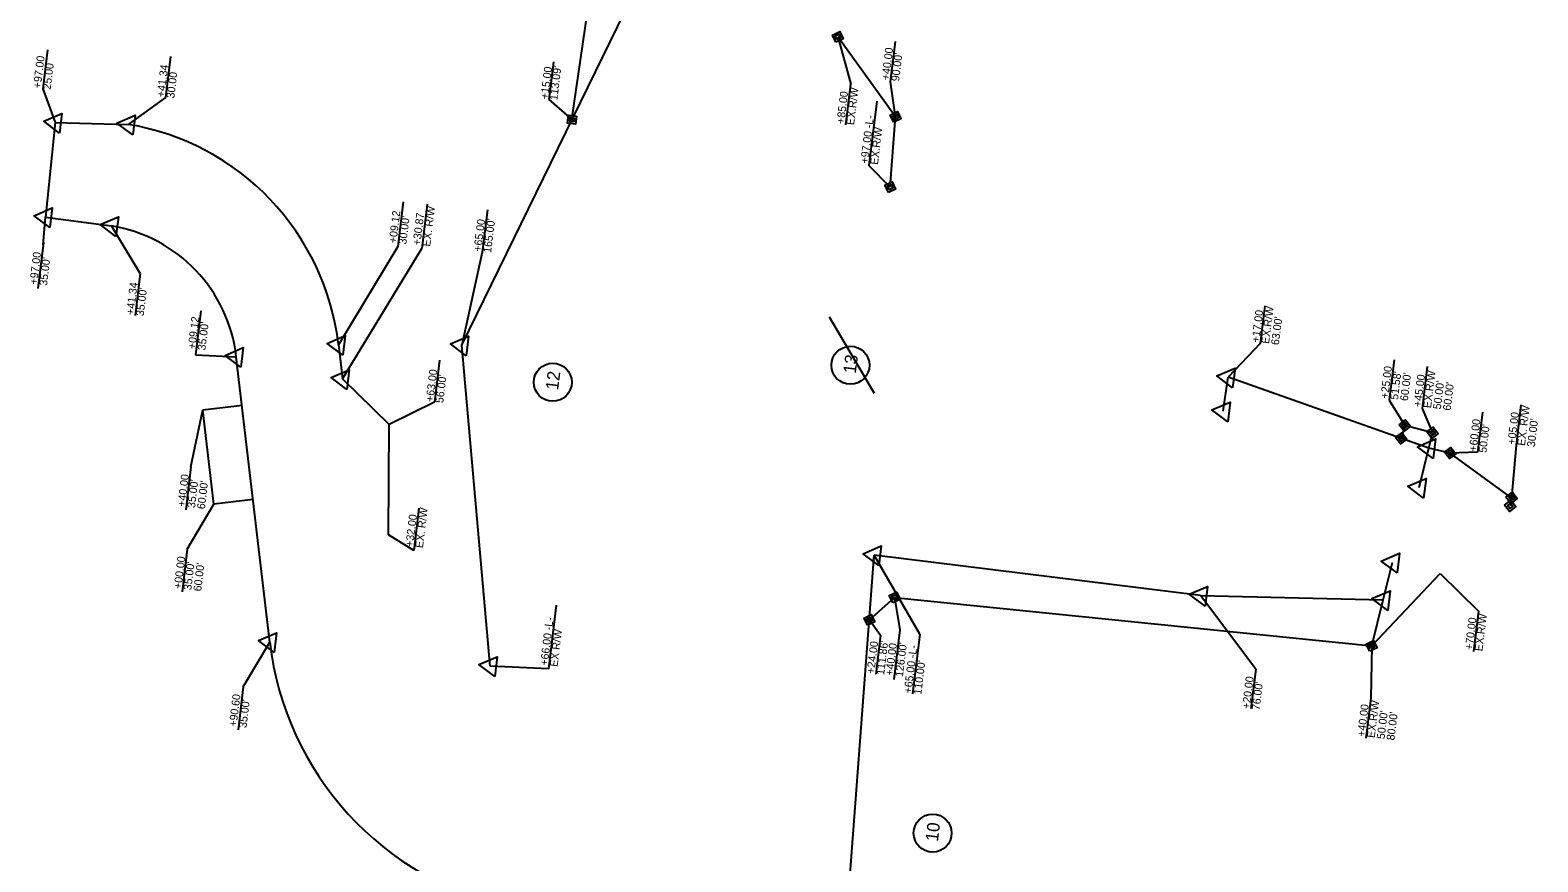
# Model space of a CAD drawing. Extents: x 474184 to 481900, y 489262 to 505659.
# Drawn here: x 480947 to 481900, y 490740 to 491265 of the extents above; entities that cross this region are included whole.
import ezdxf

# ---------------------------------------------------------------- set-up
doc = ezdxf.new("R2010")
doc.units = 0
for name, color, linetype in [('Prop Drainage Structure Box Number Symbol CELL', 7, 'Continuous'), ('Prop Drainage Structure Drop Inlet Grate 2 Wide Slots and Sag Grates 840 22 CELL', 7, 'Continuous'), ('Prop Drainage Structure Outlet Berm Ditch 850 10 Label', 7, 'Continuous'), ('Prop Drainage Structure Pipe CSP 15in', 7, 'Continuous'), ('Prop Drainage Structure Pipe RCP 18in Class IV', 7, 'Continuous'), ('Prop Drainage Structure Pipe RCP 18in Class IV Label', 7, 'Continuous'), ('Prop Drainage Structure Pipe Side Drain 15in Label', 7, 'Continuous'), ('Prop Drainage Structure Pipe Stub Out CELL', 7, 'Continuous'), ('Prop Drainage Structure Plot Symbol 50 Scale', 7, 'Continuous'), ('Prop Earthen Structure Base Ditch Lateral Detail Label', 7, 'Continuous'), ('Prop Earthen Structure False Sump CELL', 7, 'Continuous'), ('Prop Earthen Structure False Sump Label', 7, 'Continuous')]:
    doc.layers.add(name, color=color, linetype=linetype)

msp = doc.modelspace()

# ---------------------------------------------------------------- linework, layer by layer
at = {"layer": 'Prop Drainage Structure Box Number Symbol CELL'}
msp.add_line((481481.1, 491035.35), (481452.82, 491083.62), dxfattribs=at)
at = {"layer": 'Prop Drainage Structure Drop Inlet Grate 2 Wide Slots and Sag Grates 840 22 CELL'}
for p, q in [((481289.91, 491208.53), (481322.37, 491432.91)), ((481845.12, 490997.83), (481831.54, 491000.96)), ((481883.94, 490969.56), (481845.12, 490997.83)), ((481883.94, 490969.56), (481883, 490964.49))]:
    msp.add_line(p, q, dxfattribs=at)
at = {"layer": 'Prop Drainage Structure Outlet Berm Ditch 850 10 Label'}
for p, q in [((481494.51, 491210.18), (481457.98, 491260.76)), ((481491.08, 491165.82), (481494.51, 491210.18)), ((481816.35, 491015.22), (481814.11, 491007.1)), ((481833.89, 491010.67), (481816.35, 491015.22)), ((481831.54, 491000.96), (481833.89, 491010.67)), ((481477.93, 490892.4), (481493.9, 490906.57)), ((481493.9, 490906.57), (481795.45, 490875.96)), ((481795.45, 490875.96), (481802.74, 490905.06))]:
    msp.add_line(p, q, dxfattribs=at)
at = {"layer": 'Prop Drainage Structure Pipe CSP 15in'}
for p, q in [((481465.93, 491053.29), (481465.93, 491053.29)), ((481277.77, 491042.54), (481277.77, 491042.54)), ((481517.9, 490757.64), (481517.9, 490757.64))]:
    msp.add_line(p, q, dxfattribs=at)
for centre in [(481465.93, 491053.29), (481277.77, 491042.54), (481517.9, 490757.64)]:
    msp.add_circle(centre, 12, dxfattribs=at)
at = {"layer": 'Prop Drainage Structure Pipe RCP 18in Class IV'}
for p, q in [((481457.98, 491260.76), (481457.98, 491260.76)), ((481289.91, 491208.53), (481289.91, 491208.53)), ((481494.51, 491210.18), (481494.51, 491210.18)), ((480963.14, 491206.59), (480963.14, 491206.59)), ((481009.43, 491205.47), (481009.43, 491205.47)), ((481491.08, 491165.82), (481491.08, 491165.82)), ((480957.06, 491146.9), (480957.06, 491146.9)), ((480998.85, 491141.33), (480998.85, 491141.33)), ((481142.3, 491066.22), (481142.3, 491066.22)), ((481220.2, 491065.93), (481220.2, 491065.93)), ((481077.74, 491058.66), (481077.74, 491058.66)), ((481704.75, 491045.65), (481704.75, 491045.65)), ((481144.84, 491044.62), (481144.84, 491044.62)), ((481701.64, 491024.2), (481701.64, 491024.2)), ((481816.35, 491015.22), (481816.35, 491015.22)), ((481833.89, 491010.67), (481833.89, 491010.67)), ((481814.11, 491007.1), (481814.11, 491007.1)), ((481831.54, 491000.96), (481831.54, 491000.96)), ((481845.12, 490997.83), (481845.12, 490997.83)), ((481825.49, 490976.02), (481825.49, 490976.02)), ((481883.94, 490969.56), (481883.94, 490969.56)), ((481883, 490964.49), (481883, 490964.49)), ((481481.05, 490933.33), (481481.05, 490933.33)), ((481808.67, 490928.71), (481808.67, 490928.71)), ((481493.9, 490906.57), (481493.9, 490906.57)), ((481687.27, 490907.72), (481687.27, 490907.72)), ((481802.74, 490905.06), (481802.74, 490905.06)), ((481477.93, 490892.4), (481477.93, 490892.4)), ((481098.87, 490878.41), (481098.87, 490878.41)), ((481795.45, 490875.96), (481795.45, 490875.96)), ((481238.27, 490863.24), (481238.27, 490863.24))]:
    msp.add_line(p, q, dxfattribs=at)
for points in [[(480965.95, 491199.95), (480955.99, 491207.47), (480967.47, 491212.36)], [(481012.25, 491198.83), (481002.28, 491206.34), (481013.76, 491211.23)], [(480959.88, 491140.26), (480949.91, 491147.77), (480961.39, 491152.67)], [(481001.67, 491134.69), (480991.7, 491142.21), (481003.18, 491147.1)], [(481145.12, 491059.58), (481135.16, 491067.1), (481146.63, 491071.99)], [(481223.02, 491059.29), (481213.06, 491066.8), (481224.54, 491071.69)], [(481080.56, 491052.02), (481070.6, 491059.53), (481082.08, 491064.43)], [(481147.65, 491037.98), (481137.69, 491045.49), (481149.17, 491050.39)], [(481707.57, 491039.01), (481697.61, 491046.53), (481709.08, 491051.42)], [(481704.45, 491017.56), (481694.49, 491025.08), (481705.97, 491029.97)], [(481834.35, 490994.32), (481824.39, 491001.83), (481835.87, 491006.72)], [(481828.31, 490969.38), (481818.34, 490976.89), (481829.82, 490981.79)], [(481483.87, 490926.68), (481473.91, 490934.2), (481485.38, 490939.09)], [(481811.49, 490922.07), (481801.52, 490929.58), (481813, 490934.47)], [(481690.09, 490901.08), (481680.13, 490908.6), (481691.6, 490913.49)], [(481805.56, 490898.42), (481795.6, 490905.93), (481807.07, 490910.83)], [(481101.69, 490871.77), (481091.72, 490879.29), (481103.2, 490884.18)], [(481241.08, 490856.6), (481231.12, 490864.12), (481242.6, 490869.01)]]:
    msp.add_lwpolyline(points, close=True, dxfattribs=at)
at = {"layer": 'Prop Drainage Structure Pipe RCP 18in Class IV Label'}
for points in [[(481456.81, 491257.36), (481454.58, 491261.93), (481459.16, 491264.16), (481461.39, 491259.59)], [(481457.4, 491259.06), (481456.28, 491261.35), (481458.57, 491262.46), (481459.69, 491260.17)], [(481292.75, 491210.75), (481292.13, 491205.69), (481287.08, 491206.31), (481287.7, 491211.36)], [(481291.33, 491209.64), (481291.02, 491207.11), (481288.5, 491207.42), (481288.81, 491209.95)], [(481493.34, 491206.78), (481491.11, 491211.35), (481495.68, 491213.58), (481497.91, 491209.01)], [(481493.92, 491208.48), (481492.81, 491210.77), (481495.1, 491211.88), (481496.21, 491209.59)], [(481489.91, 491162.42), (481487.68, 491167), (481492.26, 491169.23), (481494.49, 491164.65)], [(481490.5, 491164.12), (481489.38, 491166.41), (481491.67, 491167.53), (481492.79, 491165.24)], [(481812.77, 491015.66), (481816.78, 491018.79), (481819.92, 491014.78), (481815.91, 491011.65)], [(481814.56, 491015.44), (481816.57, 491017.01), (481818.13, 491015), (481816.13, 491013.43)], [(481810.54, 491007.54), (481814.54, 491010.67), (481817.68, 491006.66), (481813.67, 491003.53)], [(481812.32, 491007.32), (481814.33, 491008.89), (481815.89, 491006.88), (481813.89, 491005.31)], [(481830.32, 491011.11), (481834.33, 491014.25), (481837.47, 491010.24), (481833.46, 491007.1)], [(481832.11, 491010.89), (481834.11, 491012.46), (481835.68, 491010.46), (481833.67, 491008.89)], [(481841.55, 490998.27), (481845.56, 491001.4), (481848.69, 490997.39), (481844.69, 490994.26)], [(481843.34, 490998.05), (481845.34, 490999.62), (481846.91, 490997.61), (481844.9, 490996.04)], [(481880.36, 490970), (481884.37, 490973.14), (481887.51, 490969.13), (481883.5, 490965.99)], [(481882.15, 490969.78), (481884.16, 490971.35), (481885.72, 490969.34), (481883.72, 490967.78)], [(481879.43, 490964.93), (481883.44, 490968.06), (481886.57, 490964.05), (481882.56, 490960.92)], [(481881.21, 490964.71), (481883.22, 490966.28), (481884.78, 490964.27), (481882.78, 490962.7)], [(481492.73, 490903.17), (481490.5, 490907.74), (481495.08, 490909.97), (481497.31, 490905.4)], [(481493.32, 490904.87), (481492.2, 490907.16), (481494.49, 490908.27), (481495.61, 490905.98)], [(481476.76, 490889), (481474.53, 490893.57), (481479.1, 490895.8), (481481.34, 490891.23)], [(481477.35, 490890.7), (481476.23, 490892.99), (481478.52, 490894.1), (481479.63, 490891.82)], [(481794.28, 490872.56), (481792.04, 490877.13), (481796.62, 490879.37), (481798.85, 490874.79)], [(481794.86, 490874.26), (481793.75, 490876.55), (481796.03, 490877.66), (481797.15, 490875.38)]]:
    msp.add_lwpolyline(points, close=True, dxfattribs=at)
at = {"layer": 'Prop Drainage Structure Pipe Side Drain 15in Label'}
for p, q in [((481220.2, 491065.93), (481362.08, 491356.15)), ((480963.14, 491206.59), (480957.06, 491146.9)), ((480963.14, 491206.59), (481009.43, 491205.47)), ((480957.06, 491146.9), (480998.85, 491141.33)), ((481142.3, 491066.22), (481144.84, 491044.62)), ((481238.27, 490863.24), (481220.2, 491065.93)), ((481098.87, 490878.41), (481077.74, 491058.66)), ((481701.64, 491024.2), (481704.75, 491045.65)), ((481831.54, 491000.96), (481704.75, 491045.65)), ((481825.49, 490976.02), (481831.54, 491000.96)), ((481447.56, 490494.15), (481481.05, 490933.33)), ((481687.27, 490907.72), (481481.05, 490933.33)), ((481802.74, 490905.06), (481808.67, 490928.71)), ((481687.27, 490907.72), (481802.74, 490905.06))]:
    msp.add_line(p, q, dxfattribs=at)
for centre, radius, start, end in [((480983.39, 491047.6), 160, 6.6848, 80.63395), ((480983.39, 491047.6), 95, 6.6848, 80.63395), ((481292.54, 490901.11), 195, 186.6848, 258.08974)]:
    msp.add_arc(centre, radius, start, end, dxfattribs=at)
at = {"layer": 'Prop Drainage Structure Pipe Stub Out CELL'}
for p, q in [((481174.4, 491015.74), (481144.84, 491044.62)), ((481056.51, 491025.08), (481081.34, 491027.99)), ((481056.51, 491025.08), (481056.51, 491025.08)), ((481063.49, 490965.49), (481056.51, 491025.08)), ((481174.01, 490946.22), (481174.4, 491015.74)), ((481088.32, 490968.4), (481063.49, 490965.49)), ((481088.32, 490968.4), (481088.32, 490968.4)), ((481795.45, 490875.96), (481838.82, 490921.79))]:
    msp.add_line(p, q, dxfattribs=at)
at = {"layer": 'Prop Drainage Structure Plot Symbol 50 Scale'}
for p, q in [((480958.38, 491252.57), (480955.37, 491227.88)), ((481036.09, 491248.27), (481032.92, 491222.38)), ((481183.27, 491156.45), (481179.84, 491128.39)), ((481198.35, 491155.08), (481194.93, 491127.02)), ((481236.43, 491151.42), (481233.18, 491124.76)), ((480955.87, 491130.74), (480952.34, 491101.87)), ((481144.84, 491044.62), (481194.93, 491127.02)), ((481016.96, 491111.34), (481013.72, 491084.78)), ((481055.38, 491087.77), (481051.98, 491059.91)), ((481725.14, 491067.32), (481728.16, 491090.87)), ((481830.63, 491052.57), (481827.37, 491025.87)), ((481722.15, 490861.27), (481687.27, 490907.72)), ((481279.89, 490901.59), (481274.99, 490861.42)), ((481509.76, 490883.27), (481505.16, 490845.63)), ((481722.15, 490861.27), (481719.11, 490836.41)), ((481082.13, 490850.03), (481078.83, 490822.98))]:
    msp.add_line(p, q, dxfattribs=at)
for points in [[(480955.37, 491227.88), (480963.14, 491206.59)], [(481032.92, 491222.38), (481009.43, 491205.47)], [(480955.69, 491129.31), (480957.06, 491146.9)], [(481016.96, 491111.34), (480998.85, 491141.33)], [(481179.84, 491128.39), (481142.3, 491066.22)], [(481233.18, 491124.76), (481220.2, 491065.93)], [(481725.14, 491067.32), (481704.75, 491045.65)], [(481051.98, 491059.91), (481077.74, 491058.66)], [(481827.37, 491025.87), (481833.89, 491010.67)], [(481509.76, 490883.27), (481481.05, 490933.33)], [(481082.13, 490850.03), (481098.87, 490878.41)], [(481274.99, 490861.42), (481238.27, 490863.24)]]:
    msp.add_lwpolyline(points, dxfattribs=at)
at = {"layer": 'Prop Earthen Structure Base Ditch Lateral Detail Label'}
for p, q in [((481457.98, 491260.76), (481466.13, 491230.83)), ((481491.24, 491232.35), (481494.39, 491257.91)), ((481463.01, 491205.26), (481466.13, 491230.83)), ((481494.51, 491210.18), (481491.24, 491232.35)), ((481482.69, 491220.1), (481477.55, 491179.5)), ((481491.08, 491165.82), (481477.55, 491179.5)), ((481809.57, 491056.64), (481806.54, 491031.23)), ((481806.54, 491031.23), (481816.35, 491015.22)), ((481493.9, 490906.57), (481497.27, 490886.17)), ((481477.93, 490892.4), (481484.97, 490882.66)), ((481497.27, 490886.17), (481493.43, 490854.67)), ((481484.97, 490882.66), (481481.94, 490858.01)), ((481795.45, 490875.96), (481794.89, 490843.01)), ((481794.89, 490843.01), (481791.86, 490817.59))]:
    msp.add_line(p, q, dxfattribs=at)
at = {"layer": 'Prop Earthen Structure False Sump CELL'}
for p, q in [((481278.19, 491245.01), (481275.27, 491221.14)), ((481889.83, 491028.19), (481886.74, 491002.82)), ((481865.42, 491023.58), (481862.35, 490998.43)), ((481862.35, 490998.43), (481845.12, 490997.83))]:
    msp.add_line(p, q, dxfattribs=at)
for points in [[(481275.27, 491221.14), (481289.91, 491208.53)], [(481886.74, 491002.82), (481883.94, 490969.56)]]:
    msp.add_lwpolyline(points, dxfattribs=at)
at = {"layer": 'Prop Earthen Structure False Sump Label'}
for p, q in [((481206.18, 491056.6), (481202.92, 491029.86)), ((481049.06, 490989.05), (481045.76, 490962)), ((481193.1, 490962.88), (481189.86, 490936.33)), ((481046.75, 490937.11), (481043.45, 490910.05)), ((481838.82, 490921.79), (481862.94, 490897.8)), ((481862.94, 490897.8), (481859.91, 490872.38))]:
    msp.add_line(p, q, dxfattribs=at)
for points in [[(481202.92, 491029.86), (481174.4, 491015.74)], [(481049.06, 490989.05), (481056.51, 491025.08)], [(481046.75, 490937.11), (481063.49, 490965.49)], [(481189.86, 490936.33), (481174.01, 490946.22)]]:
    msp.add_lwpolyline(points, dxfattribs=at)

# ---------------------------------------------------------------- texts
at = {"layer": 'Prop Drainage Structure Pipe CSP 15in'}
for s, p in [('13', (481469.28, 491047.71)), ('12', (481281.16, 491037.27)), ('10', (481521.25, 490752.06))]:
    msp.add_text(s, height=8, rotation=83.03651, dxfattribs=at).set_placement(p)
at = {"layer": 'Prop Drainage Structure Plot Symbol 50 Scale'}
for s, rotation, p in [('+97.00', 83.03651, (480954.13, 491228.04)), ('25.00', 83.03651, (480960.33, 491227.28)), ('+41.34', 83.03651, (481032.28, 491222.46)), ('30.00', 83.03651, (481038.49, 491221.7)), ('+09.12 ', 83.03651, (481178.98, 491130.2)), ('EX. R/W', 83.03651, (481200.27, 491128.07)), ("30.00'", 83.03651, (481185.18, 491129.44)), ('+30.87 ', 83.03651, (481194.07, 491128.82)), ('+65.00 ', 83.03651, (481232.56, 491124.84)), ("165.00'", 83.03651, (481238.76, 491124.08)), ('+97.00', 83.03651, (480951.84, 491104.07)), ("35.00'", 83.03651, (480958.04, 491103.32)), ('+41.34', 83.03651, (481012.94, 491084.89)), ("35.00'", 83.03651, (481019.14, 491084.13)), ('+09.12 ', 83.03651, (481051.93, 491063.26)), ('+17.00 ', 82.69213, (481724.35, 491067.42)), ('EX.R/W', 82.69213, (481730.55, 491066.62)), ("63.00'", 82.69213, (481736.75, 491065.83)), ("35.00'", 83.03651, (481058.13, 491062.51)), ('+45.00 ', 83.03651, (481826.74, 491026.71)), ('EX.R/W', 83.03651, (481832.94, 491025.95)), ("50.00'", 83.03651, (481839.14, 491025.19)), ("60.00'", 83.03651, (481845.35, 491024.43)), ('+66.00 -L-', 83.03651, (481274.6, 490863.28)), ('EX R/W', 83.03651, (481280.8, 490862.53)), ('+65.00 -L-', 83.03651, (481504.54, 490845.71)), ("110.00'", 83.03651, (481510.74, 490844.95)), ('+20.00 ', 83.03651, (481718.38, 490835.9)), ('+90.60 ', 83.03651, (481077.94, 490824.69)), ("76.00'", 83.03651, (481724.58, 490835.15)), ("35.00'", 83.03651, (481084.14, 490823.94))]:
    msp.add_text(s, height=5, rotation=rotation, dxfattribs=at).set_placement(p)
at = {"layer": 'Prop Earthen Structure Base Ditch Lateral Detail Label'}
for s, rotation, p in [('+40.00', 83.0608, (481490.48, 491233.22)), ("90.00' ", 83.0608, (481496.68, 491232.47)), ('EX.R/W ', 83.0608, (481468.22, 491204.84)), ('+85.00', 83.0608, (481462.01, 491205.6)), ('+97.00 -L-', 83.03651, (481477.12, 491180.52)), ('EX.R/W ', 83.03651, (481483.33, 491179.76)), ('+25.00', 83.0608, (481805.86, 491031.97)), ("51.58'", 83.0608, (481812.06, 491031.22)), ("60.00'", 83.0608, (481818.27, 491030.46)), ('+24.00', 83.0608, (481481.01, 490858.12)), ("111.86' ", 83.0608, (481487.22, 490857.37)), ('+40.00', 83.0608, (481492.88, 490856.95)), ("126.00'", 83.0608, (481499.09, 490856.2)), ('+40.00', 83.0608, (481791.15, 490818.34)), ('EX.R/W', 83.0608, (481797.35, 490817.58)), ("50.00'", 83.0608, (481803.56, 490816.83)), ("80.00'", 83.0608, (481809.76, 490816.07))]:
    msp.add_text(s, height=5, rotation=rotation, dxfattribs=at).set_placement(p)
at = {"layer": 'Prop Earthen Structure False Sump CELL'}
for s, p in [('+15.00', (481274.88, 491221.19)), ("113.09'", (481280.63, 491220.49)), ('EX. R/W', (481892.32, 491002.14)), ('+60.00', (481861.73, 490998.5)), ('+05.00 ', (481886.12, 491002.9)), ("30.00'", (481898.52, 491001.38)), ("50.00'", (481867.93, 490997.75))]:
    msp.add_text(s, height=5, rotation=83.03651, dxfattribs=at).set_placement(p)
at = {"layer": 'Prop Earthen Structure False Sump Label'}
for s, height, rotation, p in [('+63.00', 5, 83.03651, (481202.3, 491029.93)), ("56.00'", 5, 83.03651, (481208.5, 491029.17)), ('+40.00', 5, 83.03651, (481045.37, 490963.65)), ("35.00'", 5, 83.03651, (481051.57, 490962.89)), ("60.00'", 5, 83.03651, (481057.77, 490962.13)), ('EX. R/W', 5.004, 83.03651, (481195.68, 490937.54)), ('+32.00', 5.004, 83.03651, (481189.47, 490938.3)), ('+00.00', 5, 83.03651, (481043.06, 490911.71)), ("35.00'", 5, 83.03651, (481049.26, 490910.95)), ("60.00'", 5, 83.03651, (481055.47, 490910.19)), ('+70.00', 5, 83.0608, (481859.25, 490873.13)), ('EX.R/W', 5, 83.0608, (481865.45, 490872.37))]:
    msp.add_text(s, height=height, rotation=rotation, dxfattribs=at).set_placement(p)

doc.saveas('drawing.dxf')
